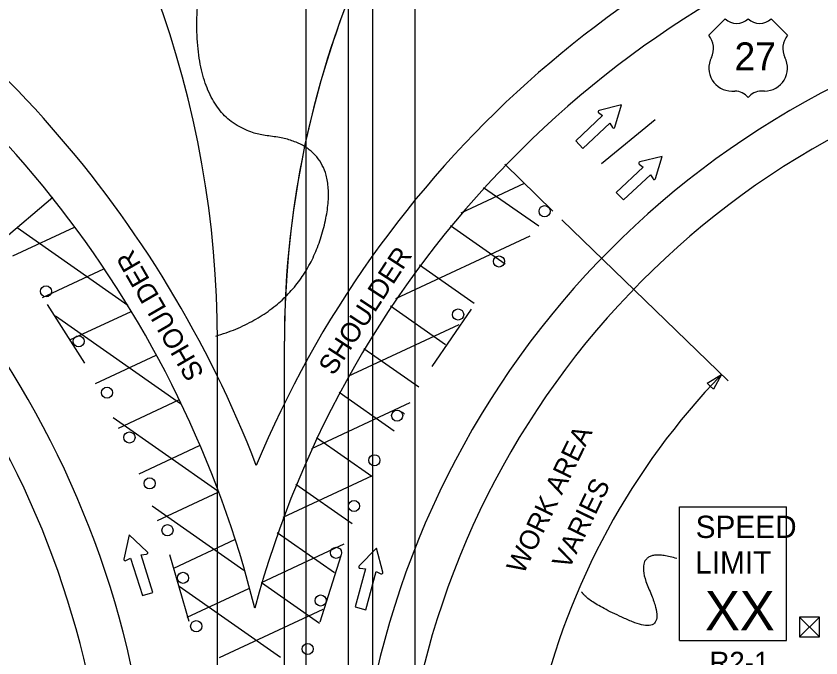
# Model space of a CAD drawing. Extents: x 16563 to 19504, y 6261 to 8279.
# Drawn here: x 16876.6 to 17165.8, y 7830.1 to 8060.6 of the extents above; entities that cross this region are included whole.
import ezdxf

# ---------------------------------------------------------------- set-up
doc = ezdxf.new("R2010")
doc.units = 0
for name, color, linetype in [('ALI_LEGAL_EX', 7, 'Continuous'), ('MT_SCRATCH_LEVEL_A', 7, 'Continuous'), ('MT_SCRATCH_LEVEL_E', 7, 'Continuous'), ('PAVT_EDGE_EX', 7, 'Continuous'), ('TRAFFIC_SIGNS_PR', 7, 'Continuous'), ('TYPICAL_EX', 7, 'Continuous'), ('TYPICAL_TEXT_DIMEN_PR', 7, 'Continuous')]:
    doc.layers.add(name, color=color, linetype=linetype)

msp = doc.modelspace()

# ---------------------------------------------------------------- linework, layer by layer
at = {"layer": 'ALI_LEGAL_EX'}
for p, q in [((16980.68, 8278.53), (16980.68, 7460.39)), ((17004.68, 8278.53), (17004.68, 7460.39)), ((16995.95, 8243.16), (16995.95, 7425.02)), ((17019.95, 8243.16), (17019.95, 7425.02)), ((16949.01, 7333.59), (16949.01, 7943.78)), ((16973.01, 7443.44), (16973.01, 7943.78)), ((16973.01, 7333.59), (16973.01, 7943.78)), ((16973.01, 7333.59), (16973.01, 7943.78))]:
    msp.add_line(p, q, dxfattribs=at)
for points in [[(17086.92, 8007.59), (17106.22, 8023.47)], [(16901.32, 7935.93), (16887.96, 7957.06)], [(17026.12, 7934.69), (17040.2, 7955.35)], [(16938.84, 7843.13), (16931.89, 7867.15)], [(16985.91, 7843.08), (16993.41, 7866.93)]]:
    msp.add_lwpolyline(points, dxfattribs=at)
for centre, radius, start, end in [((17313.01, 7943.78), 340, 129.5666, 180), ((16585.01, 7943.78), 364, 0, 40.1909), ((17313.01, 7943.78), 340, 137.516, 180)]:
    msp.add_arc(centre, radius, start, end, dxfattribs=at)
at = {"layer": 'MT_SCRATCH_LEVEL_A'}
for p, q in [((17069.43, 7990.55), (17052.28, 8007.34)), ((17036.54, 7989.94), (17059.24, 8000.53)), ((17064.4, 7985.08), (17044.6, 7998.94)), ((16889.81, 7995.4), (16871.52, 7979.86)), ((16875.47, 7974.42), (16897.61, 7984.74)), ((16916.76, 7956.61), (16876.96, 7984.48)), ((17052.39, 7971.51), (17032.75, 7985.26)), ((17013.12, 7959.16), (17061.3, 7981.63)), ((16886.12, 7959.52), (16908.15, 7969.79)), ((17041.23, 7957.35), (17021.59, 7971.1)), ((17030.96, 7942.57), (17011.17, 7956.42)), ((16935.75, 7921.34), (16890.76, 7952.84)), ((16895.98, 7944.26), (16917.96, 7954.51)), ((16995.91, 7931.27), (17035.77, 7949.86)), ((17021.33, 7927.34), (17001.62, 7941.14)), ((16905.17, 7928.68), (16926.93, 7938.83)), ((17012.46, 7911.58), (16992.75, 7925.38)), ((16913.37, 7912.65), (16935.05, 7922.76)), ((16982.83, 7905.32), (17018.17, 7921.79)), ((17016.14, 7917.68), (17015.49, 7918.32)), ((16949.12, 7890.01), (16911.54, 7916.32)), ((17004.47, 7895.2), (16984.57, 7909.13)), ((16920.81, 7896.26), (16942.49, 7906.36)), ((16972.64, 7880.7), (17004.69, 7895.65)), ((16997.35, 7878.2), (16977.11, 7892.38)), ((16927.44, 7879.49), (16949.24, 7889.65)), ((16958.45, 7861.5), (16925.5, 7884.57)), ((16991.06, 7860.64), (16970.48, 7875.05)), ((16933.25, 7862.34), (16955.22, 7872.58)), ((16964.79, 7857.18), (16994.55, 7871.06)), ((16985.62, 7842.47), (16964.76, 7857.08)), ((16971.6, 7830.31), (16935.21, 7855.79)), ((16938.15, 7844.76), (16960.27, 7855.07)), ((16949.76, 7830.31), (16986.99, 7847.67))]:
    msp.add_line(p, q, dxfattribs=at)
at = {"layer": 'MT_SCRATCH_LEVEL_E'}
for p, q in [((17094.17, 8028.66), (17086.08, 8026.71)), ((17094.17, 8028.66), (17086.08, 8026.71)), ((17091.73, 8020.68), (17094.17, 8028.66)), ((17091.73, 8020.68), (17094.17, 8028.66)), ((17087.35, 8024.81), (17077.69, 8015.74)), ((17087.35, 8024.81), (17077.69, 8015.74)), ((17085.91, 8025.89), (17087.35, 8024.81)), ((17085.91, 8025.89), (17087.35, 8024.81)), ((17080.24, 8013.01), (17089.92, 8022.08)), ((17080.24, 8013.01), (17089.92, 8022.08)), ((17089.92, 8022.08), (17090.9, 8020.57)), ((17089.92, 8022.08), (17090.9, 8020.57)), ((17077.69, 8015.74), (17080.24, 8013.01)), ((17077.69, 8015.74), (17080.24, 8013.01)), ((17108.77, 8010.19), (17100.67, 8008.24)), ((17108.77, 8010.19), (17100.67, 8008.24)), ((17106.32, 8002.21), (17108.77, 8010.19)), ((17106.32, 8002.21), (17108.77, 8010.19)), ((17100.5, 8007.42), (17101.95, 8006.33)), ((17100.5, 8007.42), (17101.95, 8006.33)), ((17101.95, 8006.33), (17092.28, 7997.27)), ((17101.95, 8006.33), (17092.28, 7997.27)), ((17094.84, 7994.54), (17104.51, 8003.6)), ((17094.84, 7994.54), (17104.51, 8003.6)), ((17104.51, 8003.6), (17105.49, 8002.09)), ((17104.51, 8003.6), (17105.49, 8002.09)), ((17092.28, 7997.27), (17094.84, 7994.54)), ((17092.28, 7997.27), (17094.84, 7994.54))]:
    msp.add_line(p, q, dxfattribs=at)
for centre, start, end in [((17086.19, 8026.26), 103.5817, 233.1207), ((17086.19, 8026.26), 103.5817, 233.1207), ((17091.28, 8020.83), 213.193, 342.93), ((17091.28, 8020.83), 213.193, 342.93), ((17100.79, 8007.78), 103.5817, 233.1207), ((17100.79, 8007.78), 103.5817, 233.1207), ((17105.88, 8002.36), 213.193, 342.93), ((17105.88, 8002.36), 213.193, 342.93)]:
    msp.add_arc(centre, 0.463, start, end, dxfattribs=at)
at = {"layer": 'PAVT_EDGE_EX'}
for centre, radius, start, end in [((17314.02, 7753.78), 380, 106.2376, 157.5011), ((16586.02, 7753.78), 404, 21.0961, 61.5719), ((17314.02, 7753.78), 364, 106.2376, 165.0045), ((16586.02, 7753.78), 388, 14.0482, 61.5719), ((17314.02, 7753.78), 316, 106.2376, 180), ((16586.02, 7753.78), 340, 0, 61.5719), ((17314.02, 7753.78), 300, 106.2376, 180), ((16586.02, 7753.78), 324, 0, 61.5719)]:
    msp.add_arc(centre, radius, start, end, dxfattribs=at)
at = {"layer": 'TRAFFIC_SIGNS_PR'}
for p, q in [((17115.03, 7884.31), (17153.43, 7884.31)), ((17115.03, 7836.31), (17115.03, 7884.31)), ((17153.43, 7836.31), (17153.43, 7884.31)), ((17115.03, 7836.31), (17153.43, 7836.31))]:
    msp.add_line(p, q, dxfattribs=at)
for centre in [(17066.51, 7990.5), (17050.15, 7972.45), (16887.38, 7961.75), (17035.44, 7953.41), (16899.12, 7943.78), (16909.31, 7925.35), (17013.54, 7917.11), (16917.36, 7909.25), (17005.37, 7901.08), (16924.6, 7892.77), (16998.04, 7884.64), (16931.02, 7875.96), (16991.6, 7867.84), (16936.61, 7858.85), (16986.04, 7850.72), (16941.35, 7841.49), (16981.4, 7833.33)]:
    msp.add_circle(centre, 2, dxfattribs=at)
at = {"layer": 'TYPICAL_EX'}
for p, q in [((17125.49, 8053.69), (17131.39, 8059.58)), ((17153.79, 8053.69), (17147.89, 8059.58)), ((17133.74, 8033.63), (17134.92, 8033.63)), ((17145.54, 8033.63), (17144.37, 8033.63))]:
    msp.add_line(p, q, dxfattribs=at)
for centre, radius, start, end in [((17135.51, 8063.87), 5.96, 226.1404, 313.8596), ((17143.77, 8063.88), 5.96, 226.1404, 313.8596), ((17119.9, 8048.96), 7.31, 333.0977, 40.1936), ((17159.38, 8048.96), 7.31, 139.8064, 206.9023), ((17133.75, 8041.87), 8.24, 152.6698, 269.9013), ((17145.53, 8041.87), 8.24, 270.0987, 27.3302), ((17134.93, 8027.72), 5.91, 37.1038, 90.1385), ((17144.35, 8027.72), 5.91, 89.8615, 142.8962)]:
    msp.add_arc(centre, radius, start, end, dxfattribs=at)
at = {"layer": 'TYPICAL_TEXT_DIMEN_PR'}
for p, q in [((17132.42, 7929.62), (17072.68, 7987.41)), ((17124.9, 7928.74), (17130.11, 7931.86)), ((17130.11, 7931.86), (17127.16, 7926.55)), ((17126.03, 7927.65), (17124.9, 7928.74)), ((17127.16, 7926.55), (17126.03, 7927.65)), ((16917.26, 7874.29), (16915.38, 7865.61)), ((16923.78, 7868.24), (16917.26, 7874.29)), ((17006.12, 7869.46), (16999.89, 7863.12)), ((17008.4, 7860.86), (17006.12, 7869.46)), ((16916.08, 7865.07), (16917.79, 7865.96)), ((16917.79, 7865.96), (16922, 7852.46)), ((16921.6, 7867.14), (16923.51, 7867.39)), ((16925.81, 7853.64), (16921.6, 7867.14)), ((17002.12, 7862.12), (16998.48, 7848.46)), ((17000.2, 7862.29), (17002.12, 7862.12)), ((17002.33, 7847.43), (17005.97, 7861.1)), ((17005.97, 7861.1), (17007.72, 7860.28)), ((16922, 7852.46), (16925.81, 7853.64)), ((16998.48, 7848.46), (17002.33, 7847.43)), ((17158.15, 7844.78), (17165.26, 7837.66)), ((17158.15, 7837.66), (17165.26, 7844.78))]:
    msp.add_line(p, q, dxfattribs=at)
msp.add_lwpolyline([(17158.15, 7844.78), (17158.15, 7837.66), (17165.26, 7837.66), (17165.26, 7844.78)], close=True, dxfattribs=at)
for centre, radius, start, end in [((17314.02, 7753.78), 256, 135.9234, 167.0592), ((16923.44, 7867.88), 0.494, 277.3494, 47.0864), ((16915.86, 7865.51), 0.494, 167.7381, 297.277), ((17000.25, 7862.78), 0.494, 135.4939, 265.0328), ((17007.92, 7860.74), 0.494, 245.1052, 14.8421)]:
    msp.add_arc(centre, radius, start, end, dxfattribs=at)
for points in [[(16948.4, 7945.64), (16979.76, 7955.08), (16994.7, 8014.55), (16941.5, 8020.27), (16941.6, 8096.03), (16991.53, 8099.63)], [(17113.99, 7865.8), (17096.77, 7871.03), (17111.84, 7837.05), (17082.16, 7849.96), (17079.85, 7853.81)]]:
    msp.add_open_spline(points, degree=2, dxfattribs=at)

# ---------------------------------------------------------------- texts
at = {"layer": 'TRAFFIC_SIGNS_PR'}
for s, height, p in [('SPEED', 8, (17120.79, 7873.17)), ('LIMIT', 8, (17120.63, 7860.37)), ('XX', 14.031, (17124.14, 7840.07)), ('R2-1', 7.44, (17125.7, 7824.87))]:
    msp.add_text(s, height=height, dxfattribs=at).set_placement(p)
at = {"layer": 'TYPICAL_EX'}
msp.add_text('27', height=10, dxfattribs=at).set_placement((17134.75, 8041.11))
at = {"layer": 'TYPICAL_TEXT_DIMEN_PR'}
for s, rotation, p in [('SHOULDER', 120.0663, (16944.4, 7932.18)), ('SHOULDER', 56.8597, (16990.7, 7931.17)), ('WORK AREA', 64.0878, (17058.85, 7859.82)), ('VARIES', 64.0878, (17075.22, 7861.48))]:
    msp.add_text(s, height=7, rotation=rotation, dxfattribs=at).set_placement(p)

doc.saveas('drawing.dxf')
